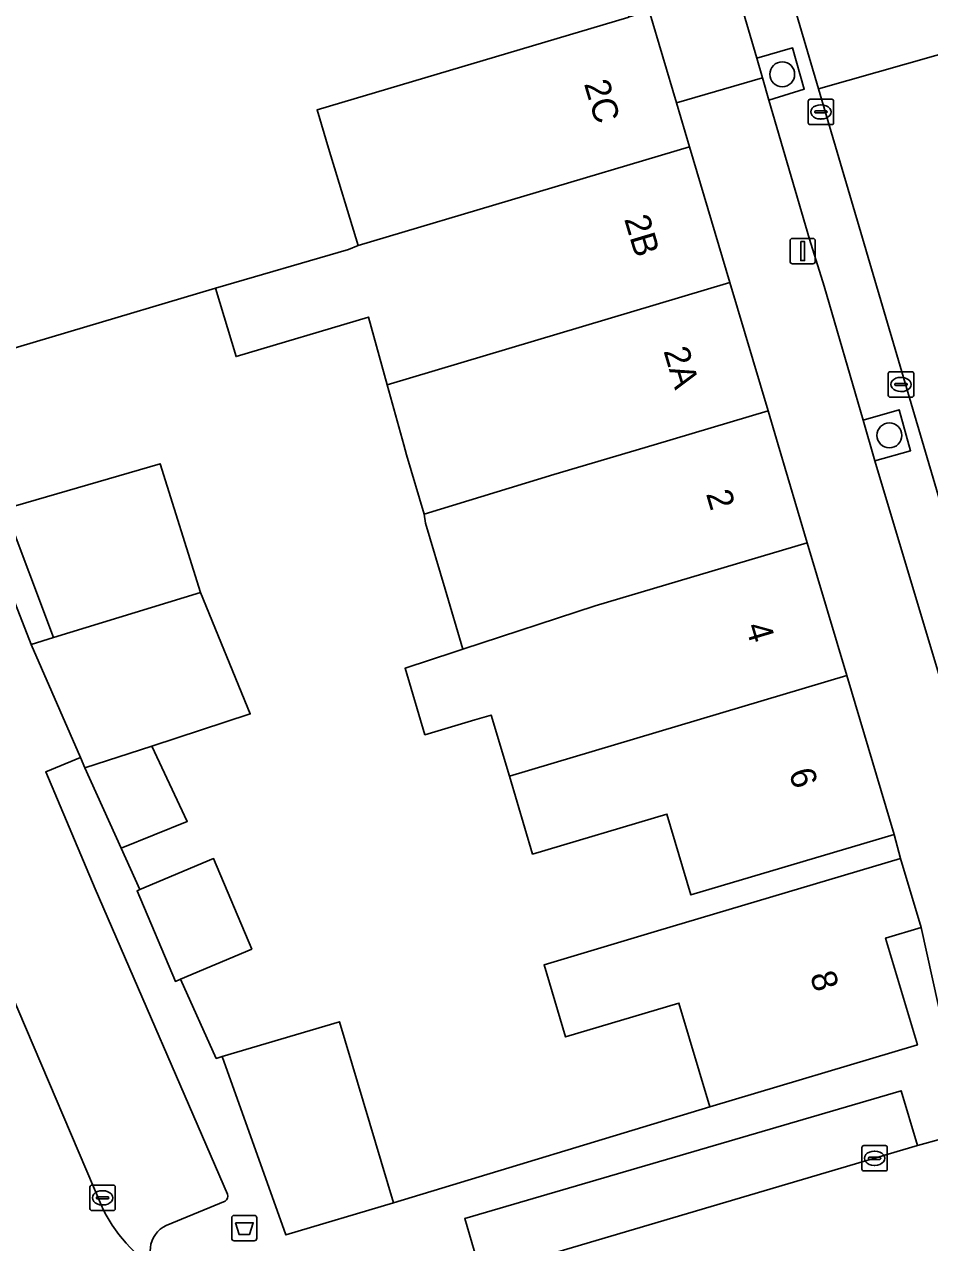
# Model space of a CAD drawing. Extents: x 159371 to 159986, y 382987 to 383597.
# Drawn here: x 159617.77 to 159653.42, y 383468.59 to 383516.55 of the extents above; entities that cross this region are included whole.
import ezdxf

# ---------------------------------------------------------------- set-up
doc = ezdxf.new("R2010")
doc.units = 0
for name, color, linetype in [('IMGEO_Afvalbak', 7, 'Continuous'), ('IMGEO_Boom', 7, 'Continuous'), ('IMGEO_Erf', 7, 'Continuous'), ('IMGEO_Groenvoorziening', 7, 'Continuous'), ('IMGEO_Kolk', 7, 'Continuous'), ('IMGEO_Lichtmast', 7, 'Continuous'), ('IMGEO_Muur', 7, 'Continuous'), ('IMGEO_Pand', 7, 'Continuous'), ('IMGEO_Pand_nummerreeks', 7, 'Continuous'), ('IMGEO_Parkeervlak_open', 7, 'Continuous'), ('IMGEO_Rijbaan_lokaal_gesloten', 7, 'Continuous'), ('IMGEO_Rijbaan_lokaal_open', 7, 'Continuous'), ('IMGEO_Voetpad_open', 7, 'Continuous')]:
    doc.layers.add(name, color=color, linetype=linetype)

msp = doc.modelspace()

# ---------------------------------------------------------------- linework, layer by layer
at = {"layer": 'IMGEO_Afvalbak'}
for p, q in [((159625.934, 383468.762), (159625.934, 383469.562)), ((159625.934, 383469.562), (159625.934, 383468.762)), ((159626.034, 383469.662), (159626.824, 383469.662)), ((159626.824, 383469.662), (159626.034, 383469.662)), ((159626.924, 383469.562), (159626.924, 383468.762)), ((159626.924, 383468.762), (159626.924, 383469.562)), ((159626.824, 383468.662), (159626.034, 383468.662)), ((159626.034, 383468.662), (159626.824, 383468.662))]:
    msp.add_line(p, q, dxfattribs=at)
msp.add_lwpolyline([(159626.077, 383469.376), (159626.781, 383469.376), (159626.632, 383468.906), (159626.226, 383468.906), (159626.077, 383469.376)], dxfattribs=at)
for centre, start, end in [((159626.034, 383469.562), 90, 180), ((159626.034, 383469.562), 90, 180), ((159626.824, 383469.562), 0, 90), ((159626.824, 383469.562), 360, 90), ((159626.034, 383468.762), 180, 270), ((159626.034, 383468.762), 180, 270), ((159626.824, 383468.762), 270, 0), ((159626.824, 383468.762), 270, 0)]:
    msp.add_arc(centre, 0.1, start, end, dxfattribs=at)
at = {"layer": 'IMGEO_Boom'}
for centre in [(159647.614, 383514.583), (159651.834, 383500.369)]:
    msp.add_circle(centre, 0.489, dxfattribs=at)
at = {"layer": 'IMGEO_Erf'}
msp.add_lwpolyline([(159616.147, 383496.962), (159618.037, 383492.137), (159618.918, 383492.407), (159617.016, 383497.483), (159623.12, 383499.253), (159624.706, 383494.183), (159626.663, 383489.402), (159622.782, 383488.14), (159624.186, 383485.174), (159621.584, 383484.116), (159622.321, 383482.487), (159625.217, 383483.712), (159626.724, 383480.146), (159623.916, 383478.958), (159625.325, 383475.842), (159625.562, 383475.912), (159630.177, 383477.286), (159632.301, 383470.154), (159644.76, 383473.936), (159643.545, 383478.019), (159639.081, 383476.69), (159638.236, 383479.531), (159642.699, 383480.86), (159652.275, 383483.712), (159652.02, 383484.662), (159644.018, 383482.28), (159643.071, 383485.461), (159637.781, 383483.886), (159636.868, 383486.953), (159636.152, 383489.36), (159635.511, 383489.169), (159633.541, 383488.582), (159632.761, 383491.203), (159634.715, 383491.843), (159635.041, 383491.952), (159634.337, 383494.314), (159633.561, 383496.919), (159633.517, 383497.27), (159632.823, 383499.6), (159632.711, 383500), (159632.051, 383502.361), (159631.324, 383505.024), (159626.104, 383503.47), (159625.3, 383506.17), (159613.656, 383502.703)], dxfattribs=at)
at = {"layer": 'IMGEO_Groenvoorziening'}
for points in [[(159648.021, 383515.624), (159646.608, 383515.216), (159646.834, 383514.444), (159647.09, 383513.567), (159648.48, 383514)], [(159651.26, 383499.365), (159652.671, 383499.762), (159652.215, 383501.375), (159650.804, 383500.962)]]:
    msp.add_lwpolyline(points, close=True, dxfattribs=at)
at = {"layer": 'IMGEO_Kolk'}
for p, q in [((159648.711, 383513.603), (159649.563, 383513.603)), ((159648.636, 383512.677), (159648.636, 383513.529)), ((159648.895, 383513.097), (159648.895, 383513.109)), ((159648.938, 383513.146), (159649.336, 383513.146)), ((159649.124, 383513.383), (159649.149, 383513.383)), ((159649.379, 383513.109), (159649.379, 383513.097)), ((159649.637, 383513.529), (159649.637, 383512.677)), ((159649.333, 383513.06), (159648.935, 383513.06)), ((159649.147, 383512.823), (159649.122, 383512.823)), ((159649.563, 383512.603), (159648.711, 383512.603)), ((159651.791, 383501.947), (159651.791, 383502.799)), ((159651.866, 383502.873), (159652.718, 383502.873)), ((159652.279, 383502.653), (159652.304, 383502.653)), ((159652.792, 383502.799), (159652.792, 383501.947)), ((159652.05, 383502.367), (159652.05, 383502.379)), ((159652.488, 383502.33), (159652.09, 383502.33)), ((159652.093, 383502.416), (159652.491, 383502.416)), ((159652.302, 383502.093), (159652.277, 383502.093)), ((159652.534, 383502.379), (159652.534, 383502.367)), ((159652.718, 383501.873), (159651.866, 383501.873)), ((159650.749, 383471.486), (159650.749, 383472.338)), ((159650.824, 383472.412), (159651.676, 383472.412)), ((159651.75, 383472.338), (159651.75, 383471.486)), ((159651.008, 383471.906), (159651.008, 383471.918)), ((159651.446, 383471.869), (159651.048, 383471.869)), ((159651.051, 383471.955), (159651.449, 383471.955)), ((159651.237, 383472.192), (159651.262, 383472.192)), ((159651.492, 383471.918), (159651.492, 383471.906)), ((159651.676, 383471.412), (159650.824, 383471.412)), ((159651.26, 383471.632), (159651.235, 383471.632)), ((159620.348, 383469.928), (159620.348, 383470.78)), ((159620.423, 383470.854), (159621.275, 383470.854)), ((159620.836, 383470.634), (159620.861, 383470.634)), ((159621.349, 383470.78), (159621.349, 383469.928)), ((159620.607, 383470.348), (159620.607, 383470.36)), ((159621.045, 383470.311), (159620.647, 383470.311)), ((159620.65, 383470.397), (159621.048, 383470.397)), ((159620.859, 383470.074), (159620.834, 383470.074)), ((159621.091, 383470.36), (159621.091, 383470.348)), ((159621.275, 383469.854), (159620.423, 383469.854))]:
    msp.add_line(p, q, dxfattribs=at)
for points in [[(159648.711, 383513.603), (159649.563, 383513.603)], [(159648.636, 383512.677), (159648.636, 383513.529)], [(159649.637, 383513.529), (159649.637, 383512.677)], [(159649.563, 383512.603), (159648.711, 383512.603)], [(159651.791, 383501.947), (159651.791, 383502.799)], [(159651.866, 383502.873), (159652.718, 383502.873)], [(159652.792, 383502.799), (159652.792, 383501.947)], [(159652.718, 383501.873), (159651.866, 383501.873)], [(159650.749, 383471.486), (159650.749, 383472.338)], [(159650.824, 383472.412), (159651.676, 383472.412)], [(159651.75, 383472.338), (159651.75, 383471.486)], [(159651.676, 383471.412), (159650.824, 383471.412)], [(159620.348, 383469.928), (159620.348, 383470.78)], [(159620.423, 383470.854), (159621.275, 383470.854)], [(159621.349, 383470.78), (159621.349, 383469.928)], [(159621.275, 383469.854), (159620.423, 383469.854)]]:
    msp.add_lwpolyline(points, dxfattribs=at)
for centre, radius, start, end in [((159648.713, 383513.527), 0.0765, 91.552, 178.448), ((159648.713, 383513.527), 0.0765, 91.552, 178.448), ((159649.561, 383513.527), 0.0765, 1.552, 88.448), ((159649.561, 383513.527), 0.0765, 1.552, 88.448), ((159648.935, 383513.106), 0.0403, 85.8775, 175.7526), ((159648.932, 383513.096), 0.0366, 178.938, 274.7102), ((159649.336, 383513.103), 0.043, 264.8664, 352.4533), ((159649.34, 383513.108), 0.0386, 1.7309, 96.639), ((159648.713, 383512.679), 0.0765, 181.552, 268.448), ((159648.713, 383512.679), 0.0765, 181.552, 268.448), ((159649.561, 383512.679), 0.0765, 271.552, 358.448), ((159649.561, 383512.679), 0.0765, 271.552, 358.448), ((159651.868, 383502.797), 0.0765, 91.552, 178.448), ((159651.868, 383502.797), 0.0765, 91.552, 178.448), ((159652.716, 383502.797), 0.0765, 1.552, 88.448), ((159652.716, 383502.797), 0.0765, 1.552, 88.448), ((159652.09, 383502.376), 0.0403, 85.8775, 175.7526), ((159652.087, 383502.366), 0.0366, 178.938, 274.7102), ((159652.491, 383502.373), 0.043, 264.8664, 352.4533), ((159652.495, 383502.378), 0.0386, 1.7309, 96.639), ((159651.868, 383501.949), 0.0765, 181.552, 268.448), ((159651.868, 383501.949), 0.0765, 181.552, 268.448), ((159652.716, 383501.949), 0.0765, 271.552, 358.448), ((159652.716, 383501.949), 0.0765, 271.552, 358.448), ((159650.826, 383472.336), 0.0765, 91.552, 178.448), ((159650.826, 383472.336), 0.0765, 91.552, 178.448), ((159651.674, 383472.336), 0.0765, 1.552, 88.448), ((159651.674, 383472.336), 0.0765, 1.552, 88.448), ((159651.048, 383471.915), 0.0403, 85.8775, 175.7526), ((159651.045, 383471.905), 0.0366, 178.938, 274.7102), ((159651.449, 383471.912), 0.043, 264.8664, 352.4533), ((159651.453, 383471.917), 0.0386, 1.7309, 96.639), ((159650.826, 383471.488), 0.0765, 181.552, 268.448), ((159650.826, 383471.488), 0.0765, 181.552, 268.448), ((159651.674, 383471.488), 0.0765, 271.552, 358.448), ((159651.674, 383471.488), 0.0765, 271.552, 358.448), ((159620.425, 383470.778), 0.0765, 91.552, 178.448), ((159620.425, 383470.778), 0.0765, 91.552, 178.448), ((159621.273, 383470.778), 0.0765, 1.552, 88.448), ((159621.273, 383470.778), 0.0765, 1.552, 88.448), ((159620.425, 383469.93), 0.0765, 181.552, 268.448), ((159620.425, 383469.93), 0.0765, 181.552, 268.448), ((159620.647, 383470.357), 0.0403, 85.8775, 175.7526), ((159620.644, 383470.347), 0.0366, 178.938, 274.7102), ((159621.048, 383470.354), 0.043, 264.8664, 352.4533), ((159621.052, 383470.359), 0.0386, 1.7309, 96.639), ((159621.273, 383469.93), 0.0765, 271.552, 358.448), ((159621.273, 383469.93), 0.0765, 271.552, 358.448)]:
    msp.add_arc(centre, radius, start, end, dxfattribs=at)
for centre, major_axis, ratio, start_param, end_param in [((159649.123, 383513.103), (-0.387, 0.002), 0.722429, 4.712389, 7.853982), ((159649.148, 383513.103), (-0.39, 0.002), 0.717154, 1.570796, 4.712389), ((159652.278, 383502.373), (-0.387, 0.002), 0.722429, 4.712389, 7.853982), ((159652.303, 383502.373), (-0.39, 0.002), 0.717154, 1.570796, 4.712389), ((159651.236, 383471.912), (-0.387, 0.002), 0.722429, 4.712389, 7.853982), ((159651.261, 383471.912), (-0.39, 0.002), 0.717154, 1.570796, 4.712389), ((159620.835, 383470.354), (-0.387, 0.002), 0.722429, 4.712389, 7.853982), ((159620.86, 383470.354), (-0.39, 0.002), 0.717154, 1.570796, 4.712389)]:
    msp.add_ellipse(centre, major_axis=major_axis, ratio=ratio, start_param=start_param, end_param=end_param, dxfattribs=at)
at = {"layer": 'IMGEO_Lichtmast'}
for p, q in [((159647.923, 383507.224), (159647.923, 383508.024)), ((159647.923, 383508.024), (159647.923, 383507.224)), ((159648.023, 383508.124), (159648.813, 383508.124)), ((159648.813, 383508.124), (159648.023, 383508.124)), ((159648.913, 383508.024), (159648.913, 383507.224)), ((159648.913, 383507.224), (159648.913, 383508.024)), ((159648.813, 383507.124), (159648.023, 383507.124)), ((159648.023, 383507.124), (159648.813, 383507.124))]:
    msp.add_line(p, q, dxfattribs=at)
msp.add_lwpolyline([(159648.343, 383507.999), (159648.493, 383507.999), (159648.493, 383507.249), (159648.343, 383507.249), (159648.343, 383507.999)], dxfattribs=at)
for centre, start, end in [((159648.023, 383508.024), 90, 180), ((159648.023, 383508.024), 90, 180), ((159648.813, 383508.024), 0, 90), ((159648.813, 383508.024), 360, 90), ((159648.023, 383507.224), 180, 270), ((159648.023, 383507.224), 180, 270), ((159648.813, 383507.224), 270, 0), ((159648.813, 383507.224), 270, 0)]:
    msp.add_arc(centre, 0.1, start, end, dxfattribs=at)
at = {"layer": 'IMGEO_Muur'}
msp.add_lwpolyline([(159632.301, 383470.154), (159644.76, 383473.936)], dxfattribs=at)
at = {"layer": 'IMGEO_Pand'}
msp.add_lwpolyline([(159613.656, 383502.703), (159625.3, 383506.17), (159630.531, 383507.69), (159630.914, 383507.842), (159629.745, 383511.675), (159629.296, 383513.184), (159641.528, 383516.824), (159641.59, 383516.842), (159639.852, 383520.736), (159640.755, 383521.129), (159640.819, 383521.158), (159640.758, 383521.313), (159641.943, 383521.796), (159639.238, 383528.162), (159638.413, 383527.811), (159636.546, 383532.137), (159639.093, 383533.207), (159630.263, 383553.702), (159614.892, 383547.056)], dxfattribs=at)
for points in [[(159643.446, 383513.457), (159642.369, 383517.075), (159641.59, 383516.842), (159641.528, 383516.824), (159629.296, 383513.184), (159629.745, 383511.675), (159630.914, 383507.842), (159643.961, 383511.727)], [(159632.051, 383502.361), (159645.553, 383506.383), (159643.961, 383511.727), (159630.914, 383507.842), (159630.531, 383507.69), (159625.3, 383506.17), (159626.104, 383503.47), (159631.324, 383505.024)], [(159632.051, 383502.361), (159632.711, 383500), (159632.823, 383499.6), (159633.517, 383497.27), (159638.617, 383498.825), (159642.564, 383500), (159647.055, 383501.337), (159645.553, 383506.383)], [(159647.055, 383501.337), (159642.564, 383500), (159638.617, 383498.825), (159633.517, 383497.27), (159633.561, 383496.919), (159634.337, 383494.314), (159635.041, 383491.952), (159640.242, 383493.654), (159648.601, 383496.143), (159647.453, 383500)], [(159623.12, 383499.253), (159617.016, 383497.483), (159618.918, 383492.407), (159624.706, 383494.183)], [(159648.601, 383496.143), (159640.242, 383493.654), (159635.041, 383491.952), (159634.715, 383491.843), (159632.761, 383491.203), (159633.541, 383488.582), (159635.511, 383489.169), (159636.152, 383489.36), (159636.868, 383486.953), (159650.159, 383490.911)], [(159624.706, 383494.183), (159618.918, 383492.407), (159618.037, 383492.137), (159619.975, 383487.684), (159620.151, 383487.284), (159622.782, 383488.14), (159626.663, 383489.402)], [(159636.868, 383486.953), (159637.781, 383483.886), (159643.071, 383485.461), (159644.018, 383482.28), (159652.02, 383484.662), (159650.159, 383490.911)], [(159622.782, 383488.14), (159620.151, 383487.284), (159621.584, 383484.116), (159624.186, 383485.174)], [(159622.321, 383482.487), (159622.206, 383482.438), (159623.714, 383478.872), (159623.916, 383478.958), (159626.724, 383480.146), (159625.217, 383483.712)], [(159644.76, 383473.936), (159652.938, 383476.371), (159651.686, 383480.577), (159653.084, 383480.993), (159652.275, 383483.712), (159642.699, 383480.86), (159638.236, 383479.531), (159639.081, 383476.69), (159643.545, 383478.019)], [(159632.301, 383470.154), (159630.177, 383477.286), (159625.562, 383475.912), (159628.071, 383468.895)]]:
    msp.add_lwpolyline(points, close=True, dxfattribs=at)
at = {"layer": 'IMGEO_Parkeervlak_open'}
for points in [[(159651.133, 383506.926), (159650.711, 383508.356), (159649.044, 383514.017), (159643.547, 383532.683), (159641.653, 383532.125), (159645.106, 383520.362), (159646.608, 383515.216), (159648.021, 383515.624), (159648.48, 383514), (159647.09, 383513.567), (159648.688, 383508.093), (159649.269, 383506.238), (159650.804, 383500.962), (159652.215, 383501.375), (159652.671, 383499.762), (159651.26, 383499.365), (159656.215, 383482.877), (159656.273, 383482.683)], [(159656.684, 383482.073), (159658.011, 383481.347), (159658.876, 383480.639), (159651.133, 383506.926)], [(159620.558, 383482.514), (159618.609, 383487.126), (159619.975, 383487.684), (159618.037, 383492.137), (159616.147, 383496.962), (159610.379, 383494.491), (159613.468, 383487.293), (159615.469, 383482.559), (159620.789, 383470.081)], [(159625.767, 383470.502), (159620.558, 383482.514)], [(159623.359, 383469.26), (159625.673, 383470.226)]]:
    msp.add_lwpolyline(points, dxfattribs=at)
msp.add_lwpolyline([(159635.761, 383467.333), (159652.946, 383472.414), (159652.292, 383474.568), (159635.11, 383469.534)], close=True, dxfattribs=at)
for centre, radius, start, end in [((159625.571, 383470.415), 0.214, 298.3167, 24.0677), ((159626.114, 383472.477), 5.84, 204.2273, 239.9043), ((159623.781, 383468.295), 1.054, 113.6134, 235.615)]:
    msp.add_arc(centre, radius, start, end, dxfattribs=at)
at = {"layer": 'IMGEO_Rijbaan_lokaal_gesloten'}
msp.add_lwpolyline([(159656.035, 383511.517), (159654.833, 383515.586), (159654.814, 383515.652), (159649.044, 383514.017), (159650.711, 383508.356), (159651.133, 383506.926), (159658.876, 383480.639), (159664.688, 383482.28)], close=True, dxfattribs=at)
for points in [[(159620.789, 383470.081), (159615.469, 383482.559), (159613.468, 383487.293), (159610.379, 383494.491), (159606.499, 383492.829), (159606.957, 383491.544), (159604.361, 383484.773), (159580.857, 383474.678)], [(159655.507, 383467.389), (159653.902, 383472.673), (159652.946, 383472.414), (159635.761, 383467.333), (159633.888, 383466.786), (159629.437, 383465.469), (159628.334, 383465.118), (159616.423, 383461.114), (159616.184, 383461.01), (159618.472, 383455.935), (159618.983, 383456.154)]]:
    msp.add_lwpolyline(points, dxfattribs=at)
msp.add_arc((159626.114, 383472.477), 5.84, 204.2273, 239.9043, dxfattribs=at)
at = {"layer": 'IMGEO_Rijbaan_lokaal_open'}
msp.add_lwpolyline([(159638.064, 383551.313), (159638.477, 383550.021), (159641.872, 383538.476), (159643.547, 383532.683), (159649.044, 383514.017), (159654.814, 383515.652), (159654.497, 383516.812), (159652.539, 383523.424), (159651.954, 383525.424), (159650.292, 383531.106), (159647.229, 383541.58)], dxfattribs=at)
at = {"layer": 'IMGEO_Voetpad_open'}
for points in [[(159633.614, 383557.28), (159630.263, 383553.702), (159639.093, 383533.207), (159636.546, 383532.137), (159638.413, 383527.811), (159639.238, 383528.162), (159641.943, 383521.796), (159640.758, 383521.313), (159640.819, 383521.158), (159640.755, 383521.129), (159639.852, 383520.736), (159641.59, 383516.842), (159642.369, 383517.075), (159643.446, 383513.457), (159646.834, 383514.444), (159646.608, 383515.216), (159645.106, 383520.362), (159641.653, 383532.125), (159643.547, 383532.683), (159641.872, 383538.476)], [(159651.26, 383499.365), (159650.804, 383500.962), (159649.269, 383506.238), (159648.688, 383508.093), (159647.09, 383513.567), (159646.834, 383514.444), (159643.446, 383513.457), (159643.961, 383511.727), (159645.553, 383506.383), (159647.055, 383501.337), (159647.453, 383500), (159648.601, 383496.143), (159650.159, 383490.911), (159652.02, 383484.662), (159652.275, 383483.712), (159653.084, 383480.993), (159654.869, 383472.918)], [(159659.161, 383479.026), (159656.832, 383478.365), (159655.558, 383482.691), (159656.215, 383482.877), (159651.26, 383499.365)], [(159652.292, 383474.568), (159652.946, 383472.414), (159653.902, 383472.673), (159654.869, 383472.918), (159653.084, 383480.993), (159651.686, 383480.577), (159652.938, 383476.371), (159644.76, 383473.936), (159632.301, 383470.154), (159628.071, 383468.895), (159625.562, 383475.912), (159625.325, 383475.842), (159623.916, 383478.958), (159623.714, 383478.872), (159622.206, 383482.438), (159622.321, 383482.487), (159621.584, 383484.116), (159620.151, 383487.284), (159619.975, 383487.684), (159618.609, 383487.126), (159620.558, 383482.514), (159625.767, 383470.502)], [(159628.334, 383465.118), (159629.437, 383465.469), (159629.072, 383466.641), (159633.523, 383467.956), (159633.888, 383466.786), (159635.761, 383467.333), (159635.11, 383469.534), (159652.292, 383474.568)], [(159625.673, 383470.226), (159623.359, 383469.26)]]:
    msp.add_lwpolyline(points, dxfattribs=at)
for centre, radius, start, end in [((159625.571, 383470.415), 0.214, 298.3167, 24.0677), ((159623.781, 383468.295), 1.054, 113.6134, 235.615)]:
    msp.add_arc(centre, radius, start, end, dxfattribs=at)

# ---------------------------------------------------------------- texts
at = {"layer": 'IMGEO_Pand_nummerreeks'}
for s, rotation, p in [('2C', 286.5812, (159639.8, 383514.211)), ('2B', 286.5856, (159641.384, 383508.889)), ('2A', 286.5762, (159642.932, 383503.695)), ('2', 286.5757, (159644.605, 383498.07)), ('4', 286.5812, (159646.159, 383492.854)), ('6', 286.5839, (159647.867, 383487.114)), ('8', 286.5767, (159648.699, 383479.116))]:
    msp.add_text(s, height=1, rotation=rotation, dxfattribs=at).set_placement(p)

doc.saveas('drawing.dxf')
